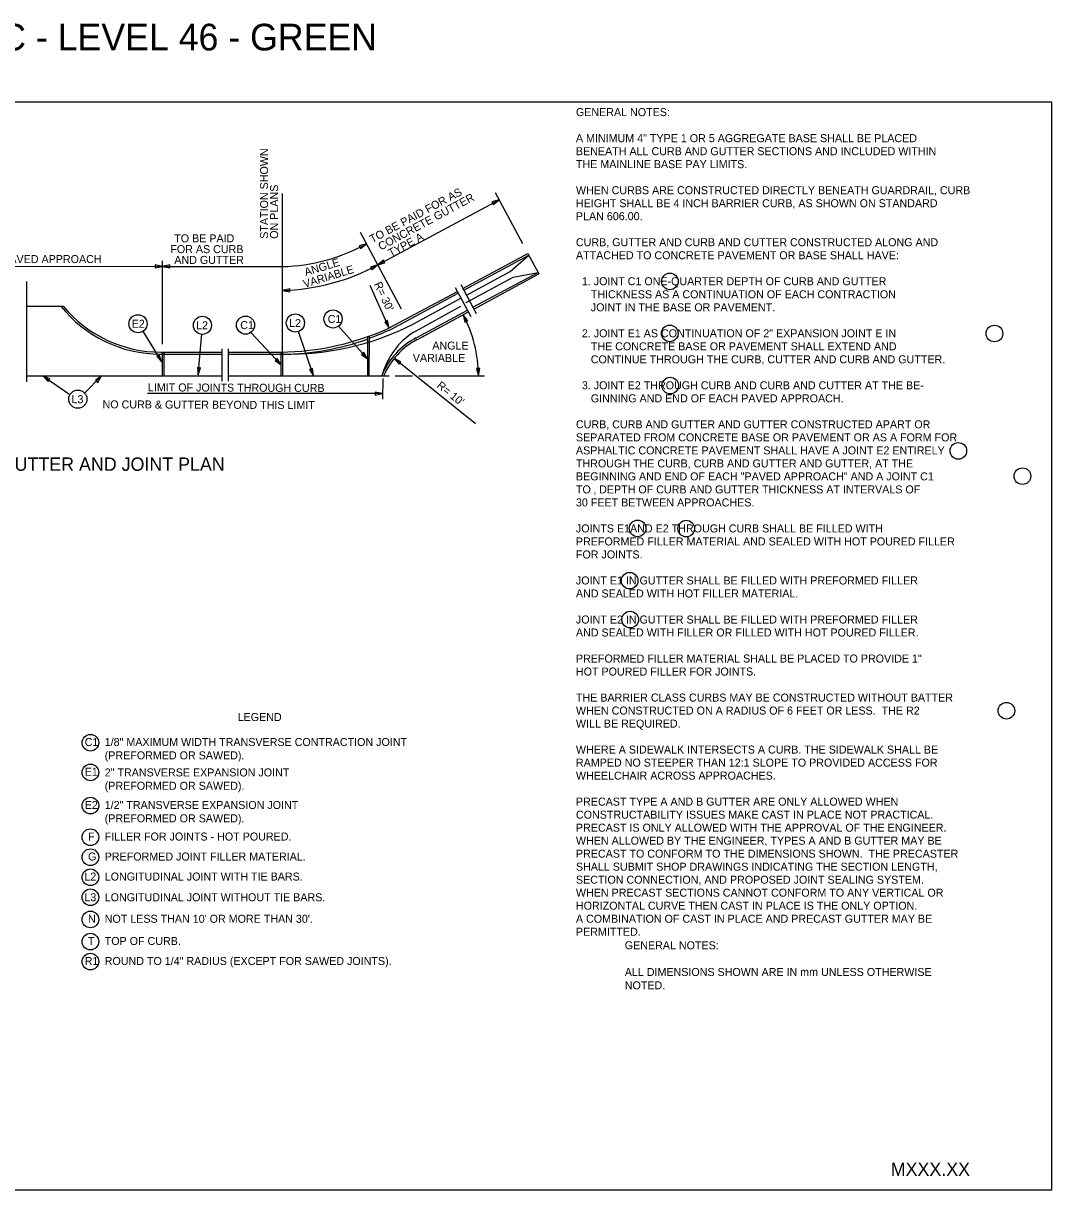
# Model space of a CAD drawing. Extents: x -439.1 to -407.9, y -458.1 to -436.2.
# Drawn here: x -427.13 to -407.86, y -458.05 to -436.2 of the extents above; entities that cross this region are included whole.
import ezdxf

# ---------------------------------------------------------------- set-up
doc = ezdxf.new("R2010")
doc.units = 0
for name, color, linetype in [('Draft_Named_Boundary', 7, 'Continuous'), ('Level 4', 7, 'Continuous'), ('Level 45', 7, 'Continuous'), ('Level 46', 7, 'Continuous')]:
    doc.layers.add(name, color=color, linetype=linetype)

msp = doc.modelspace()

# ---------------------------------------------------------------- linework, layer by layer
at = {"layer": 'Draft_Named_Boundary'}
msp.add_lwpolyline([(-439.109, -458.051), (-407.859, -458.051), (-407.859, -437.676), (-439.109, -437.676)], close=True, dxfattribs=at)
at = {"layer": 'Level 4'}
for p, q in [((-422.273, -442.394), (-422.273, -439.388)), ((-418.289, -439.364), (-417.773, -440.325)), ((-420.488, -440.724), (-418.215, -439.502)), ((-420.817, -440.113), (-420.047, -441.544)), ((-418.893, -441.165), (-417.674, -440.509)), ((-418.877, -441.197), (-417.657, -440.542)), ((-418.009, -440.847), (-417.657, -440.542)), ((-417.674, -440.509), (-417.467, -440.894)), ((-429.759, -440.748), (-424.52, -440.753)), ((-424.524, -440.752), (-424.386, -440.753)), ((-424.521, -442.208), (-424.52, -440.649)), ((-424.52, -440.753), (-422.273, -440.755)), ((-418.833, -441.431), (-417.951, -440.955)), ((-418.827, -441.29), (-418.009, -440.847)), ((-418.704, -441.518), (-417.484, -440.863)), ((-418.687, -441.55), (-417.467, -440.894)), ((-417.951, -440.955), (-417.484, -440.863)), ((-427.072, -441.035), (-427.072, -442.913)), ((-420.272, -441.906), (-420.631, -441.112)), ((-420.272, -441.905), (-418.996, -441.219)), ((-419.036, -441.145), (-418.743, -441.688)), ((-418.933, -441.09), (-418.642, -441.634)), ((-420.254, -441.938), (-418.978, -441.252)), ((-419.877, -441.86), (-418.928, -441.345)), ((-427.072, -441.497), (-426.382, -441.497)), ((-419.812, -441.983), (-418.929, -441.496)), ((-419.767, -442.089), (-418.806, -441.573)), ((-419.758, -442.127), (-418.788, -441.604)), ((-419.662, -442.075), (-418.79, -441.606)), ((-420.679, -442.485), (-421.225, -441.874)), ((-418.853, -441.796), (-418.802, -441.77)), ((-418.853, -441.796), (-418.802, -441.77)), ((-424.533, -442.542), (-424.885, -441.967)), ((-423.85, -442.786), (-423.782, -442.024)), ((-422.298, -442.597), (-422.863, -441.988)), ((-421.694, -442.804), (-421.972, -441.972)), ((-420.677, -442.072), (-420.681, -442.803)), ((-420.648, -442.072), (-420.652, -442.803)), ((-423.407, -442.296), (-423.407, -442.905)), ((-423.292, -442.296), (-423.292, -442.905)), ((-424.588, -442.394), (-423.407, -442.394)), ((-424.553, -442.358), (-423.407, -442.358)), ((-424.528, -442.358), (-424.528, -442.804)), ((-424.499, -442.358), (-424.499, -442.804)), ((-424.492, -442.372), (-424.492, -442.397)), ((-423.292, -442.358), (-422.302, -442.358)), ((-423.292, -442.394), (-422.266, -442.394)), ((-422.302, -442.364), (-422.302, -442.804)), ((-422.273, -442.364), (-422.273, -442.804)), ((-418.659, -443.699), (-420.178, -442.475)), ((-418.635, -442.667), (-418.577, -442.665)), ((-418.577, -442.665), (-418.635, -442.667)), ((-427.072, -442.804), (-423.407, -442.804)), ((-426.761, -442.804), (-426.255, -443.153)), ((-425.663, -442.804), (-425.981, -443.126)), ((-423.292, -442.804), (-420.273, -442.804)), ((-420.394, -442.855), (-420.396, -443.238)), ((-420.164, -442.804), (-419.834, -442.804)), ((-419.716, -442.804), (-418.489, -442.804)), ((-420.396, -443.135), (-424.805, -443.135))]:
    msp.add_line(p, q, dxfattribs=at)
for points in [[(-418.323, -439.593), (-418.215, -439.502), (-418.351, -439.542)], [(-420.81, -440.419), (-420.7, -440.33), (-420.836, -440.368)], [(-424.658, -440.781), (-424.52, -440.753), (-424.658, -440.724)], [(-424.382, -440.724), (-424.52, -440.753), (-424.382, -440.781)], [(-424.382, -440.724), (-424.52, -440.753), (-424.382, -440.781)], [(-422.135, -441.171), (-422.273, -441.202), (-422.134, -441.228)], [(-420.355, -441.792), (-420.272, -441.906), (-420.303, -441.768)], [(-420.355, -441.792), (-420.272, -441.906), (-420.303, -441.768)], [(-424.63, -442.439), (-424.533, -442.542), (-424.581, -442.409)], [(-422.413, -442.515), (-422.298, -442.597), (-422.371, -442.476)], [(-420.793, -442.401), (-420.679, -442.485), (-420.75, -442.363)], [(-420.053, -442.539), (-420.178, -442.475), (-420.089, -442.584)], [(-423.867, -442.645), (-423.85, -442.786), (-423.809, -442.65)], [(-421.765, -442.682), (-421.694, -442.804), (-421.711, -442.664)], [(-426.632, -442.86), (-426.761, -442.804), (-426.664, -442.907)], [(-425.733, -442.927), (-425.663, -442.804), (-425.776, -442.889)], [(-420.534, -443.164), (-420.396, -443.135), (-420.534, -443.107)]]:
    msp.add_lwpolyline(points, close=True, dxfattribs=at)
for points in [[(-420.488, -440.724), (-420.622, -440.767), (-420.594, -440.817)], [(-420.594, -440.817), (-420.488, -440.724)], [(-420.353, -440.684), (-420.38, -440.633), (-420.488, -440.724)], [(-420.488, -440.724), (-420.353, -440.684)], [(-420.488, -440.724), (-420.488, -440.724)], [(-420.488, -440.724), (-420.488, -440.724)], [(-418.802, -441.77), (-418.89, -441.659), (-418.853, -441.796)], [(-418.635, -442.667), (-418.601, -442.804)], [(-418.601, -442.804), (-418.577, -442.665)]]:
    msp.add_lwpolyline(points, dxfattribs=at)
for centre, radius in [((-415.012, -441.033), 0.156), ((-424.98, -441.826), 0.17), ((-422.031, -441.812), 0.17), ((-421.325, -441.736), 0.17), ((-423.773, -441.855), 0.17), ((-422.965, -441.852), 0.17), ((-415.016, -442.006), 0.156), ((-408.931, -442.009), 0.156), ((-415.007, -442.986), 0.156), ((-426.108, -443.239), 0.17), ((-409.608, -444.208), 0.156), ((-408.407, -444.682), 0.156), ((-415.618, -445.66), 0.156), ((-414.706, -445.665), 0.156), ((-415.767, -446.64), 0.156), ((-415.757, -447.37), 0.156), ((-425.872, -449.676), 0.156), ((-425.872, -450.233), 0.156), ((-425.872, -450.855), 0.156), ((-425.872, -451.447), 0.156), ((-425.872, -451.822), 0.156), ((-425.872, -452.197), 0.156), ((-425.872, -452.572), 0.156), ((-425.872, -452.988), 0.156), ((-425.872, -453.403), 0.156), ((-425.872, -453.778), 0.156)]:
    msp.add_circle(centre, radius, dxfattribs=at)
for centre, radius, start, end in [((-422.373, -437.259), 3.498, 271.6355, 298.5734), ((-422.373, -437.263), 3.94, 271.4732, 298.5786), ((-424.554, -439.989), 2.406, 218.7954, 269.8051), ((-424.554, -439.989), 2.369, 219.5076, 270), ((-421.02, -442.804), 2.419, 0, 28.2561), ((-422.171, -437.204), 5.191, 268.9551, 296.2234), ((-422.373, -437.263), 5.096, 270.7996, 294.3437), ((-422.373, -437.263), 5.132, 289.7222, 294.3437), ((-419.108, -443.337), 1.411, 117.8311, 157.5329), ((-419.08, -443.14), 1.369, 122.3052, 163.9782), ((-422.373, -437.27), 5.132, 271.1988, 289.2897), ((-419.108, -443.337), 1.375, 117.8311, 156.9128)]:
    msp.add_arc(centre, radius, start, end, dxfattribs=at)
at = {"layer": 'Level 45'}
msp.add_circle((-408.707, -449.077), 0.156, dxfattribs=at)

# ---------------------------------------------------------------- texts
at = {"layer": 'Level 4'}
for s, rotation, p in [('STATION SHOWN', 90, (-422.543, -440.234)), ('ON PLANS', 90, (-422.355, -440.234)), ('TO BE PAID FOR AS', 28.3, (-420.59, -440.318)), (' CONCRETE GUTTER', 28.3, (-420.478, -440.483)), ('      TYPE A', 28.3, (-420.537, -440.738)), ('VARIABLE', 17, (-421.859, -441.156)), (' ANGLE', 17, (-421.89, -440.952)), ('C1', 359.8, (-421.426, -441.811)), ('E2', 359.8, (-425.099, -441.901)), ('L2', 359.8, (-423.892, -441.929)), ('C1', 359.8, (-423.065, -441.926)), ('L2', 359.8, (-422.15, -441.887)), ('ANGLE', 359.8, (-419.465, -442.309)), ('VARIABLE', 359.8, (-419.831, -442.54)), ('LIMIT OF JOINTS THROUGH CURB', 359.8, (-424.795, -443.093)), ('L3', 359.8, (-426.227, -443.314)), ('NO CURB & GUTTER BEYOND THIS LIMIT', 359.8, (-425.645, -443.411))]:
    msp.add_text(s, height=0.15, rotation=rotation, dxfattribs=at).set_placement(p)
for s, height, p in [('TO BE PAID', 0.15, (-424.301, -440.301)), ('TO BE PAID FOR AS PAVED APPROACH', 0.15, (-429.508, -440.689)), ('FOR AS CURB', 0.15, (-424.375, -440.503)), ('AND GUTTER', 0.15, (-424.3, -440.705)), ('PLAN OF MEASUREMENT OF CURB & GUTTER AND JOINT PLAN', 0.25, (-433.683, -444.582)), ('LEGEND', 0.15, (-423.113, -449.27)), ('C1', 0.15, (-425.979, -449.738)), ('E1', 0.15, (-425.979, -450.295)), ('E2', 0.15, (-425.979, -450.918)), ('F', 0.15, (-425.917, -451.509)), ('FILLER FOR JOINTS - HOT POURED.', 0.15, (-425.604, -451.509)), ('G', 0.15, (-425.917, -451.884)), ('PREFORMED JOINT FILLER MATERIAL.', 0.15, (-425.604, -451.884)), ('L2', 0.15, (-425.986, -452.259)), ('LONGITUDINAL JOINT WITH TIE BARS.', 0.15, (-425.604, -452.259)), ('L3', 0.15, (-425.986, -452.647)), ('LONGITUDINAL JOINT WITHOUT TIE BARS.', 0.15, (-425.604, -452.647)), ('N', 0.15, (-425.917, -453.05)), ('T', 0.15, (-425.917, -453.466)), ('TOP OF CURB.', 0.15, (-425.604, -453.466)), ('R1', 0.15, (-425.979, -453.841))]:
    msp.add_text(s, height=height, dxfattribs=at).set_placement(p)
at = {"layer": 'Level 45'}
for s, p in [('GENERAL NOTES:', (-416.774, -437.936)), ('A MINIMUM 4" TYPE 1 OR 5 AGGREGATE BASE SHALL BE PLACED ', (-416.774, -438.424)), ('BENEATH ALL CURB AND GUTTER SECTIONS AND INCLUDED WITHIN ', (-416.774, -438.668)), ('THE MAINLINE BASE PAY LIMITS. ', (-416.774, -438.911)), ('WHEN CURBS ARE CONSTRUCTED DIRECTLY BENEATH GUARDRAIL, CURB ', (-416.774, -439.399)), ('HEIGHT SHALL BE 4 INCH BARRIER CURB, AS SHOWN ON STANDARD ', (-416.774, -439.643)), ('PLAN 606.00.', (-416.774, -439.886)), ('CURB, GUTTER AND CURB AND CUTTER CONSTRUCTED ALONG AND ', (-416.774, -440.374)), ('ATTACHED TO CONCRETE PAVEMENT OR BASE SHALL HAVE:', (-416.774, -440.618)), ('  1. JOINT C1 ONE-QUARTER DEPTH OF CURB AND GUTTER ', (-416.774, -441.105)), ('     THICKNESS AS A CONTINUATION OF EACH CONTRACTION ', (-416.774, -441.349)), ('     JOINT IN THE BASE OR PAVEMENT.', (-416.774, -441.593)), ('  2. JOINT E1 AS CONTINUATION OF 2" EXPANSION JOINT E IN ', (-416.774, -442.08)), ('     THE CONCRETE BASE OR PAVEMENT SHALL EXTEND AND ', (-416.774, -442.324)), ('     CONTINUE THROUGH THE CURB, CUTTER AND CURB AND GUTTER.', (-416.774, -442.568)), ('  3. JOINT E2 THROUGH CURB AND CURB AND CUTTER AT THE BE-', (-416.774, -443.055)), ('     GINNING AND END OF EACH PAVED APPROACH.', (-416.774, -443.299)), ('CURB, CURB AND GUTTER AND GUTTER CONSTRUCTED APART OR ', (-416.774, -443.786)), ('SEPARATED FROM CONCRETE BASE OR PAVEMENT OR AS A FORM FOR ', (-416.774, -444.03)), ('ASPHALTIC CONCRETE PAVEMENT SHALL HAVE A JOINT E2 ENTIRELY ', (-416.774, -444.274)), ('THROUGH THE CURB, CURB AND GUTTER AND GUTTER, AT THE ', (-416.774, -444.518)), ('BEGINNING AND END OF EACH "PAVED APPROACH" AND A JOINT C1 ', (-416.774, -444.761)), ('TO ‚ DEPTH OF CURB AND GUTTER THICKNESS AT INTERVALS OF ', (-416.774, -445.005)), ('30 FEET BETWEEN APPROACHES.', (-416.774, -445.249)), ('JOINTS E1AND E2 THROUGH CURB SHALL BE FILLED WITH ', (-416.774, -445.736)), ('PREFORMED FILLER MATERIAL AND SEALED WITH HOT POURED FILLER ', (-416.774, -445.98)), ('FOR JOINTS.', (-416.774, -446.224)), ('JOINT E1 IN GUTTER SHALL BE FILLED WITH PREFORMED FILLER ', (-416.774, -446.711)), ('AND SEALED WITH HOT FILLER MATERIAL.', (-416.774, -446.955)), ('JOINT E2 IN GUTTER SHALL BE FILLED WITH PREFORMED FILLER ', (-416.774, -447.443)), ('AND SEALED WITH FILLER OR FILLED WITH HOT POURED FILLER.', (-416.774, -447.686)), ('PREFORMED FILLER MATERIAL SHALL BE PLACED TO PROVIDE 1" ', (-416.774, -448.174)), ('HOT POURED FILLER FOR JOINTS.  ', (-416.774, -448.418)), ('THE BARRIER CLASS CURBS MAY BE CONSTRUCTED WITHOUT BATTER ', (-416.774, -448.905)), ('WHEN CONSTRUCTED ON A RADIUS OF 6 FEET OR LESS.  THE R2 ', (-416.774, -449.149)), ('WILL BE REQUIRED.', (-416.774, -449.393)), ('1/8" MAXIMUM WIDTH TRANSVERSE CONTRACTION JOINT', (-425.604, -449.738)), ('WHERE A SIDEWALK INTERSECTS A CURB. THE SIDEWALK SHALL BE ', (-416.774, -449.88)), ('(PREFORMED OR SAWED).', (-425.604, -449.988)), ('2" TRANSVERSE EXPANSION JOINT', (-425.604, -450.308)), ('RAMPED NO STEEPER THAN 12:1 SLOPE TO PROVIDED ACCESS FOR ', (-416.774, -450.124)), ('(PREFORMED OR SAWED).', (-425.604, -450.558)), ('WHEELCHAIR ACROSS APPROACHES.', (-416.774, -450.368)), ('1/2" TRANSVERSE EXPANSION JOINT', (-425.604, -450.918)), ('PRECAST TYPE A AND B GUTTER ARE ONLY ALLOWED WHEN ', (-416.774, -450.855)), ('(PREFORMED OR SAWED).', (-425.604, -451.168)), ('CONSTRUCTABILITY ISSUES MAKE CAST IN PLACE NOT PRACTICAL. ', (-416.774, -451.099)), ('PRECAST IS ONLY ALLOWED WITH THE APPROVAL OF THE ENGINEER.', (-416.774, -451.343)), ('WHEN ALLOWED BY THE ENGINEER, TYPES A AND B GUTTER MAY BE', (-416.774, -451.586)), ('PRECAST TO CONFORM TO THE DIMENSIONS SHOWN.  THE PRECASTER', (-416.774, -451.83)), ('SHALL SUBMIT SHOP DRAWINGS INDICATING THE SECTION LENGTH,  ', (-416.774, -452.074)), ('SECTION CONNECTION, AND PROPOSED JOINT SEALING SYSTEM.  ', (-416.774, -452.318)), ('WHEN PRECAST SECTIONS CANNOT CONFORM TO ANY VERTICAL OR ', (-416.774, -452.561)), ('HORIZONTAL CURVE THEN CAST IN PLACE IS THE ONLY OPTION.  ', (-416.774, -452.805)), ("NOT LESS THAN 10' OR MORE THAN 30'.", (-425.604, -453.05)), ('A COMBINATION OF CAST IN PLACE AND PRECAST GUTTER MAY BE', (-416.774, -453.049)), ('PERMITTED.', (-416.774, -453.293)), ('ROUND TO 1/4" RADIUS (EXCEPT FOR SAWED JOINTS).', (-425.604, -453.841))]:
    msp.add_text(s, height=0.15, dxfattribs=at).set_placement(p)
for s, rotation, p in [("R= 30'", 295, (-420.562, -441.082)), ("R= 10'", 321.1, (-419.394, -443.007))]:
    msp.add_text(s, height=0.15, rotation=rotation, dxfattribs=at).set_placement(p)
at = {"layer": 'Level 46'}
for s, height, p in [('METRIC - LEVEL 46 - GREEN', 0.5, (-429.642, -436.705)), ('GENERAL NOTES:', 0.15, (-415.859, -453.547)), ('ALL DIMENSIONS SHOWN ARE IN mm UNLESS OTHERWISE ', 0.15, (-415.859, -454.047)), ('NOTED.', 0.15, (-415.859, -454.297)), ('MXXX.XX', 0.25, (-410.875, -457.792))]:
    msp.add_text(s, height=height, dxfattribs=at).set_placement(p)

doc.saveas('drawing.dxf')
